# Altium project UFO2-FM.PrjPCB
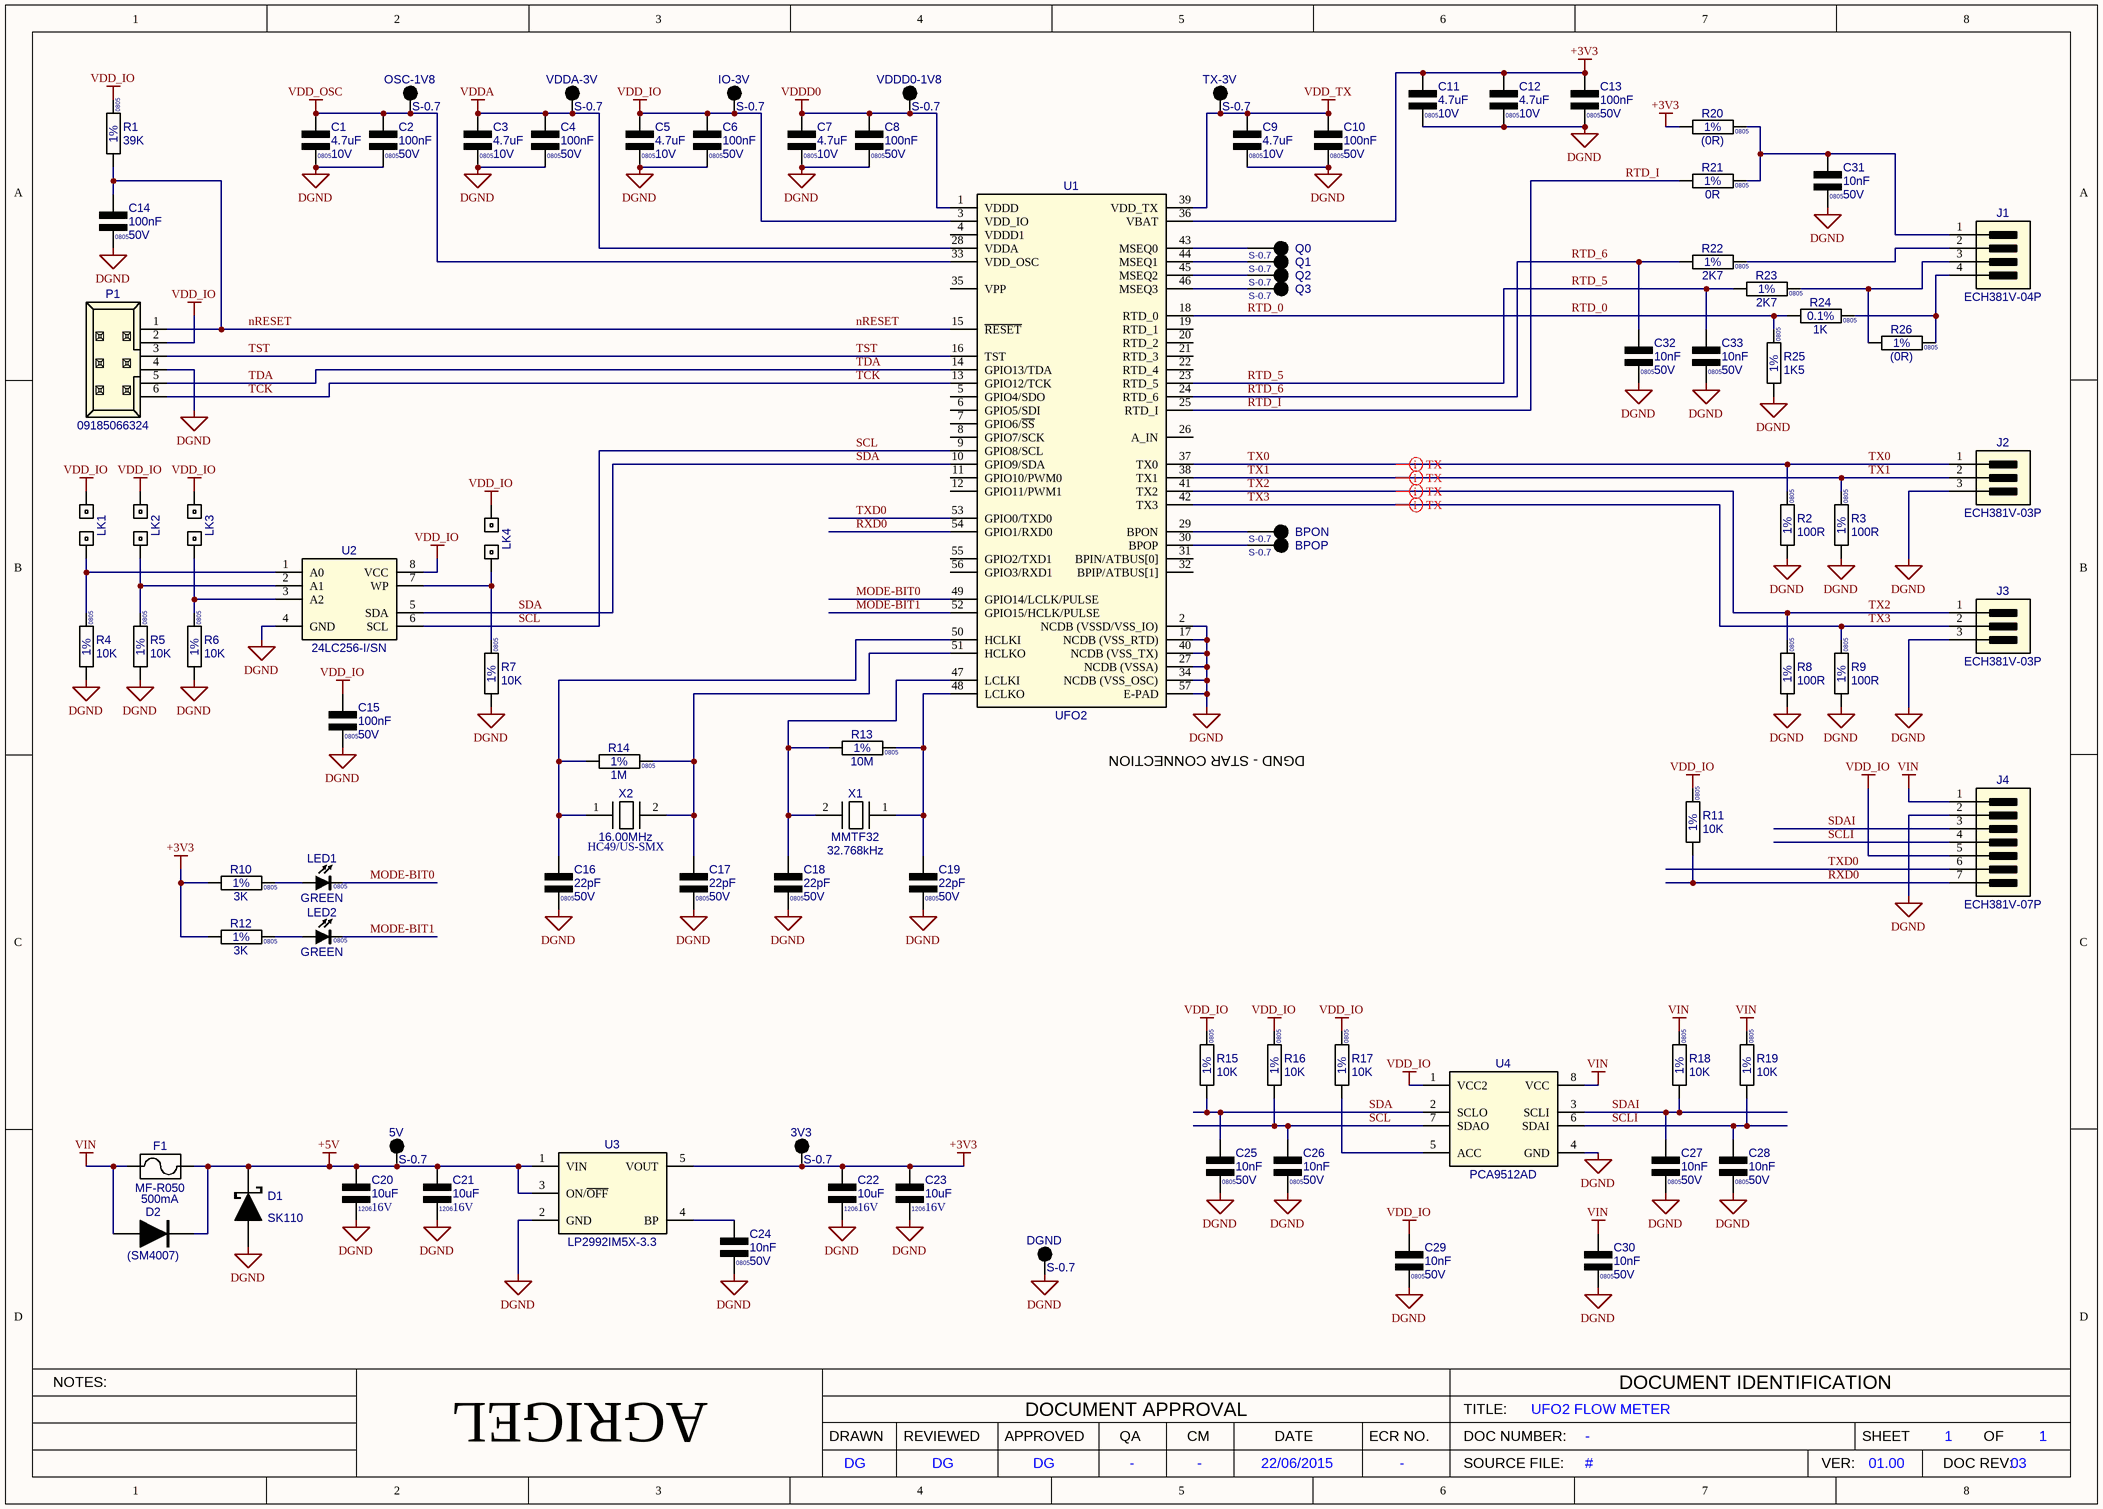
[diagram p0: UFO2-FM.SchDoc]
Version_PCB Assy Instruction: 3; Version: 01.00; Spec_Solder Mask: GREEN; Spec_Silkscreen: WHITE EPOXY; Spec_PCB Thickness: 1.60mm; Spec_Cu Thickness: 35um; SCH_Title: UFO2 FLOW METER; SCH_SheetTotal: 1; SCH_Reviewed: DG; SCH_QA: -; SCH_Number: -; SCH_FILENAME: UFO2-FM.SCH; SCH_ECR: -; SCH_DRAWN: DG; SCH_DocRev: 03; SCH_Date: 22/06/2015; SCH_CM: -; SCH_Approved: DG; PCB_TITLE: UFO2 FLOW METER PCB; PCB_Plot File [Assy]: UFO2-FM [Assy]; PCB_Plot File: UFO2-FM [Panel]; PCB_ECRNo: -; PCB_Drawn: EDM; PCB_Drawing Number: -; PCB_DocRevision: 03; PCB_Company Name: AGRIGEL
1 sheet, 93 parts. Net scope: global (net labels, ports and power ports of the same name join across sheets).
Board files: UFO2-FM.PcbDoc, UFO2-FM [Assy].PcbDoc, UFO2-FM [Panel].PcbDoc

## Sheet UFO2-FM.SchDoc: #
size A3; ApprovedBy: #; DrawnBy: #; DocumentNumber: 1; Revision: #; SheetNumber: 1; SheetTotal: 1; DocumentRevision: #; Reviewed: #; QA: #; CM: #; ECR: #; PageSetup: Record=PageOptions¦CenterHorizontal=True¦CenterVertical=True¦PrintScale=0.97¦XCorrection=1.00¦YCorrection=1.00¦PrintKind=1¦BorderSize=5000000¦LeftOffset=0¦BottomOffset=0¦Orientation=2¦PaperLength=1000¦PaperWidth=1000¦Scale=100¦PaperSource=7¦PrintQuality=-4¦MediaType=1¦DitherType=10¦PaperKind=A3¦PrintScaleMode=1

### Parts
3V3  Part Number: S-0.7  [TP-SMD-0.7MM]  (hidden comment: TP-SMD-0.7MM_V)
5V  Part Number: S-0.7  [TP-SMD-0.7MM]  (hidden comment: TP-SMD-0.7MM_V)
BPON  Part Number: S-0.7  [TP-SMD-0.7MM]  (hidden comment: TP-SMD-0.7MM)
BPOP  Part Number: S-0.7  [TP-SMD-0.7MM]  (hidden comment: TP-SMD-0.7MM)
C1  value 4.7uF  Voltage: 10V  Text1: 0805  [CAPC0805X110N]  (hidden comment: 4.7uF_C0805_10V_10%_X5R)
C2  value 100nF  Voltage: 50V  Text1: 0805  [CAPC0805X110N]  (hidden comment: 100nF_C0805_50V_10%_X7R)
C3  value 4.7uF  Voltage: 10V  Text1: 0805  [CAPC0805X110N]  (hidden comment: 4.7uF_C0805_10V_10%_X5R)
C4  value 100nF  Voltage: 50V  Text1: 0805  [CAPC0805X110N]  (hidden comment: 100nF_C0805_50V_10%_X7R)
C5  value 4.7uF  Voltage: 10V  Text1: 0805  [CAPC0805X110N]  (hidden comment: 4.7uF_C0805_10V_10%_X5R)
C6  value 100nF  Voltage: 50V  Text1: 0805  [CAPC0805X110N]  (hidden comment: 100nF_C0805_50V_10%_X7R)
C7  value 4.7uF  Voltage: 10V  Text1: 0805  [CAPC0805X110N]  (hidden comment: 4.7uF_C0805_10V_10%_X5R)
C8  value 100nF  Voltage: 50V  Text1: 0805  [CAPC0805X110N]  (hidden comment: 100nF_C0805_50V_10%_X7R)
C9  value 4.7uF  Voltage: 10V  Text1: 0805  [CAPC0805X110N]  (hidden comment: 4.7uF_C0805_10V_10%_X5R)
C10  value 100nF  Voltage: 50V  Text1: 0805  [CAPC0805X110N]  (hidden comment: 100nF_C0805_50V_10%_X7R)
C11  value 4.7uF  Voltage: 10V  Text1: 0805  [CAPC0805X110N]  (hidden comment: 4.7uF_C0805_10V_10%_X5R)
C12  value 4.7uF  Voltage: 10V  Text1: 0805  [CAPC0805X110N]  (hidden comment: 4.7uF_C0805_10V_10%_X5R)
C13  value 100nF  Voltage: 50V  Text1: 0805  [CAPC0805X110N]  (hidden comment: 100nF_C0805_50V_10%_X7R)
C14  value 100nF  Voltage: 50V  Text1: 0805  [CAPC0805X110N]  (hidden comment: 100nF_C0805_50V_10%_X7R)
C15  value 100nF  Voltage: 50V  Text1: 0805  [CAPC0805X110N]  (hidden comment: 100nF_C0805_50V_10%_X7R)
C16  value 22pF  Voltage: 50V  Text1: 0805  [CAPC0805X110N]  (hidden comment: 22pF_C0805_50V_10%_X7R)
C17  value 22pF  Voltage: 50V  Text1: 0805  [CAPC0805X110N]  (hidden comment: 22pF_C0805_50V_10%_X7R)
C18  value 22pF  Voltage: 50V  Text1: 0805  [CAPC0805X110N]  (hidden comment: 22pF_C0805_50V_10%_X7R)
C19  value 22pF  Voltage: 50V  Text1: 0805  [CAPC0805X110N]  (hidden comment: 22pF_C0805_50V_10%_X7R)
C20  value 10uF  Voltage: 16V  Text1: 1206  [CAPC1206X178N]  (hidden comment: 10uF_C1206_16V_5%_X7R)
C21  value 10uF  Voltage: 16V  Text1: 1206  [CAPC1206X178N]  (hidden comment: 10uF_C1206_16V_5%_X7R)
C22  value 10uF  Voltage: 16V  Text1: 1206  [CAPC1206X178N]  (hidden comment: 10uF_C1206_16V_5%_X7R)
C23  value 10uF  Voltage: 16V  Text1: 1206  [CAPC1206X178N]  (hidden comment: 10uF_C1206_16V_5%_X7R)
C24  value 10nF  Voltage: 50V  Text1: 0805  [CAPC0805X110N]  (hidden comment: 10nF_C0805_50V_10%_X7R)
C25  value 10nF  Voltage: 50V  Text1: 0805  [CAPC0805X110N]  (hidden comment: 10nF_C0805_50V_10%_X7R)
C26  value 10nF  Voltage: 50V  Text1: 0805  [CAPC0805X110N]  (hidden comment: 10nF_C0805_50V_10%_X7R)
C27  value 10nF  Voltage: 50V  Text1: 0805  [CAPC0805X110N]  (hidden comment: 10nF_C0805_50V_10%_X7R)
C28  value 10nF  Voltage: 50V  Text1: 0805  [CAPC0805X110N]  (hidden comment: 10nF_C0805_50V_10%_X7R)
C29  value 10nF  Voltage: 50V  Text1: 0805  [CAPC0805X110N]  (hidden comment: 10nF_C0805_50V_10%_X7R)
C30  value 10nF  Voltage: 50V  Text1: 0805  [CAPC0805X110N]  (hidden comment: 10nF_C0805_50V_10%_X7R)
C31  value 10nF  Voltage: 50V  Text1: 0805  [CAPC0805X110N]  (hidden comment: 10nF_C0805_50V_10%_X7R)
C32  value 10nF  Voltage: 50V  Text1: 0805  [CAPC0805X110N]  (hidden comment: 10nF_C0805_50V_10%_X7R)
C33  value 10nF  Voltage: 50V  Text1: 0805  [CAPC0805X110N]  (hidden comment: 10nF_C0805_50V_10%_X7R)
D1  Part Number: SK110  [SMA]  (hidden comment: SK110_SMA)
D2  value (SM4007)  [DO-213AB]  (hidden comment: SM4007-DNF)
DGND  Part Number: S-0.7  [TP-SMD-0.7MM]  (hidden comment: TP-SMD-0.7MM_V)
F1  value 500mA  [MF-R110]  (hidden comment: MF-R050)
IO-3V  Part Number: S-0.7  [TP-SMD-0.7MM]  (hidden comment: TP-SMD-0.7MM_V)
J1  ECH381V-04P  [ECH381V-04P]
J2  ECH381V-03P  [ECH381V-03P]
J3  ECH381V-03P  [ECH381V-03P]
J4  ECH381V-07P  [ECH381V-07P]
LED1  value GREEN  Text2: 0805  [LED0805-Green]  (hidden comment: GREEN_0805_SMD)
LED2  value GREEN  Text2: 0805  [LED0805-Green]  (hidden comment: GREEN_0805_SMD)
LK1  Link-THP-2.54-2PIN  [Link-THP-2.54-2PIN]  (value not drawn)
LK2  Link-THP-2.54-2PIN  [Link-THP-2.54-2PIN]  (value not drawn)
LK3  Link-THP-2.54-2PIN  [Link-THP-2.54-2PIN]  (value not drawn)
LK4  Link-THP-2.54-2PIN  [Link-THP-2.54-2PIN]  (value not drawn)
OSC-1V8  Part Number: S-0.7  [TP-SMD-0.7MM]  (hidden comment: TP-SMD-0.7MM_V)
P1  09185066324  [09185066324]
Q0  Part Number: S-0.7  [TP-SMD-0.7MM]  (hidden comment: TP-SMD-0.7MM)
Q1  Part Number: S-0.7  [TP-SMD-0.7MM]  (hidden comment: TP-SMD-0.7MM)
Q2  Part Number: S-0.7  [TP-SMD-0.7MM]  (hidden comment: TP-SMD-0.7MM)
Q3  Part Number: S-0.7  [TP-SMD-0.7MM]  (hidden comment: TP-SMD-0.7MM)
R1  value 39K  Tol: 1%  Text1: 0805  [RESC0805X65N]  (hidden comment: 39K_R0805_1%)
R2  value 100R  Tol: 1%  Text1: 0805  [RESC0805X65N]  (hidden comment: 100R_R0805_1%)
R3  value 100R  Tol: 1%  Text1: 0805  [RESC0805X65N]  (hidden comment: 100R_R0805_1%)
R4  value 10K  Tol: 1%  Text1: 0805  [RESC0805X65N]  (hidden comment: 10K_R0805_1%)
R5  value 10K  Tol: 1%  Text1: 0805  [RESC0805X65N]  (hidden comment: 10K_R0805_1%)
R6  value 10K  Tol: 1%  Text1: 0805  [RESC0805X65N]  (hidden comment: 10K_R0805_1%)
R7  value 10K  Tol: 1%  Text1: 0805  [RESC0805X65N]  (hidden comment: 10K_R0805_1%)
R8  value 100R  Tol: 1%  Text1: 0805  [RESC0805X65N]  (hidden comment: 100R_R0805_1%)
R9  value 100R  Tol: 1%  Text1: 0805  [RESC0805X65N]  (hidden comment: 100R_R0805_1%)
R10  value 3K  Tol: 1%  Text1: 0805  [RESC0805X65N]  (hidden comment: 3K_R0805_1%)
R11  value 10K  Tol: 1%  Text1: 0805  [RESC0805X65N]  (hidden comment: 10K_R0805_1%)
R12  value 3K  Tol: 1%  Text1: 0805  [RESC0805X65N]  (hidden comment: 3K_R0805_1%)
R13  value 10M  Tol: 1%  Text1: 0805  [RESC0805X65N]  (hidden comment: 10M_R0805_1%)
R14  value 1M  Tol: 1%  Text1: 0805  [RESC0805X65N]  (hidden comment: 1M_R0805_1%)
R15  value 10K  Tol: 1%  Text1: 0805  [RESC0805X65N]  (hidden comment: 10K_R0805_1%)
R16  value 10K  Tol: 1%  Text1: 0805  [RESC0805X65N]  (hidden comment: 10K_R0805_1%)
R17  value 10K  Tol: 1%  Text1: 0805  [RESC0805X65N]  (hidden comment: 10K_R0805_1%)
R18  value 10K  Tol: 1%  Text1: 0805  [RESC0805X65N]  (hidden comment: 10K_R0805_1%)
R19  value 10K  Tol: 1%  Text1: 0805  [RESC0805X65N]  (hidden comment: 10K_R0805_1%)
R20  value (0R)  Tol: 1%  Text1: 0805  [RESC0805X65N]  (hidden comment: 0R[NEQ]_R0805_1%)
R21  value 0R  Tol: 1%  Text1: 0805  [RESC0805X65N]  (hidden comment: 0R_R0805_1%)
R22  value 2K7  Tol: 1%  Text1: 0805  [RESC0805X65N]  (hidden comment: 2K7_R0805_1%)
R23  value 2K7  Tol: 1%  Text1: 0805  [RESC0805X65N]  (hidden comment: 2K7_R0805_1%)
R24  value 1K  Tol: 0.1%  Text1: 0805  [RESC0805X65N]  (hidden comment: 1K_R0805_0.1%)
R25  value 1K5  Tol: 1%  Text1: 0805  [RESC0805X65N]  (hidden comment: 1K5_R0805_1%)
R26  value (0R)  Tol: 1%  Text1: 0805  [RESC0805X65N]  (hidden comment: 0R[NEQ]_R0805_1%)
TX-3V  Part Number: S-0.7  [TP-SMD-0.7MM]  (hidden comment: TP-SMD-0.7MM_V)
U1  UFO2  [QFN56-8x8-EP]
U2  24LC256-I/SN  [SO8]
U3  LP2992IM5X-3.3  [SOT23-5]
U4  PCA9512AD  [SO8]
VDDA-3V  Part Number: S-0.7  [TP-SMD-0.7MM]  (hidden comment: TP-SMD-0.7MM_V)
VDDD0-1V8  Part Number: S-0.7  [TP-SMD-0.7MM]  (hidden comment: TP-SMD-0.7MM_V)
X1  32.768kHz  [MMTF32]
X2  Text2: HC49/US-SMX  Text1: 16.00MHz  [HC49/US-SMX-4.2]  (hidden comment: XTAL_16.00MHz-ACT-HC49/US-SMX)

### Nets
+3V3: 3V3.1 C11.1 C12.1 C13.1 C22.1 C23.1 R10.1 R12.1 R20.1 U1.36(VBAT) U3.5(VOUT)
+5V: 5V.1 C20.1 C21.1 D1.1(C) D2.1(C) F1.2 U3.1(VIN) U3.3(ON/~{OFF})
DGND: C1.2 C2.2 C3.2 C4.2 C5.2 C6.2 C7.2 C8.2 C9.2 C10.2 C11.2 C12.2 C13.2 C14.2 C15.2 C16.2 C17.2 C18.2 C19.2 C20.2 C21.2 C22.2 C23.2 C24.2 C25.2 C26.2 C27.2 C28.2 C29.2 C30.2 C31.2 C32.2 C33.2 D1.2(A) DGND.1 J2.3 J3.3 J4.2 P1.4 R2.2 R3.2 R4.2 R5.2 R6.2 R7.2 R8.2 R9.2 R25.2 U1.2(NCDB_(VSSD/VSS_IO)) U1.17(NCDB_(VSS_RTD)) U1.27(NCDB_(VSSA)) U1.34(NCDB_(VSS_OSC)) U1.40(NCDB_(VSS_TX)) U1.57(E-PAD) U2.4(GND) U3.2(GND) U4.4(GND)
VDD_IO: C5.1 C6.1 C15.1 C29.1 IO-3V.1 J4.5 LK1.1 LK2.1 LK3.1 LK4.1 P1.2 R1.1 R11.1 R15.1 R16.1 R17.1 U1.3(VDD_IO) U2.8(VCC) U4.1(VCC2)
VDD_OSC: C1.1 C2.1 OSC-1V8.1 U1.33(VDD_OSC)
VDD_TX: C9.1 C10.1 TX-3V.1 U1.39(VDD_TX)
VDDA: C3.1 C4.1 U1.28(VDDA) VDDA-3V.1
VDDD0: C7.1 C8.1 U1.1(VDDD) VDDD0-1V8.1
VIN: C30.1 D2.2(A) F1.1 J4.1 R18.1 R19.1 U4.8(VCC)
MODE-BIT0: LED1.1(K) U1.49(GPIO14/LCLK/PULSE)
MODE-BIT1: LED2.1(K) U1.52(GPIO15/HCLK/PULSE)
nRESET: C14.1 P1.1 R1.2 U1.15(~{RESET})
RTD_0: R24.1 R25.1 U1.18(RTD_0)
RTD_5: C33.1 R23.1 U1.23(RTD_5)
RTD_6: C32.1 R22.1 U1.24(RTD_6)
RTD_I: R21.1 U1.25(RTD_I)
RXD0: J4.7 R11.2 U1.54(GPIO1/RXD0)
SCL: C26.1 R16.2 U1.9(GPIO8/SCL) U2.6(SCL) U4.7(SDAO)
SCLI: C28.1 J4.4 R19.2 U4.6(SDAI)
SDA: C25.1 R15.2 U1.10(GPIO9/SDA) U2.5(SDA) U4.2(SCLO)
SDAI: C27.1 J4.3 R18.2 U4.3(SCLI)
TCK: P1.6 U1.13(GPIO12/TCK)
TDA: P1.5 U1.14(GPIO13/TDA)
TST: P1.3 U1.16(TST)
TX0: J2.1 R2.1 U1.37(TX0)
TX1: J2.2 R3.1 U1.38(TX1)
TX2: J3.1 R8.1 U1.41(TX2)
TX3: J3.2 R9.1 U1.42(TX3)
TXD0: J4.6 U1.53(GPIO0/TXD0)
NetBPON_1: BPON.1 U1.29(BPON)
NetBPOP_1: BPOP.1 U1.30(BPOP)
NetC16_1: C16.1 R14.1 U1.50(HCLKI) X2.1
NetC17_1: C17.1 R14.2 U1.51(HCLKO) X2.2
NetC18_1: C18.1 R13.1 U1.47(LCLKI) X1.2
NetC19_1: C19.1 R13.2 U1.48(LCLKO) X1.1
NetC24_1: C24.1 U3.4(BP)
NetC31_1: C31.1 J1.1 R20.2 R21.2
NetJ1_2: J1.2 R22.2
NetJ1_3: J1.3 R23.2 R26.1
NetJ1_4: J1.4 R24.2 R26.2
NetLED1_2: LED1.2(A) R10.2
NetLED2_2: LED2.2(A) R12.2
NetLK1_2: LK1.2 R4.1 U2.1(A0)
NetLK2_2: LK2.2 R5.1 U2.2(A1)
NetLK3_2: LK3.2 R6.1 U2.3(A2)
NetLK4_2: LK4.2 R7.1 U2.7(WP)
NetQ0_1: Q0.1 U1.43(MSEQ0)
NetQ1_1: Q1.1 U1.44(MSEQ1)
NetQ2_1: Q2.1 U1.45(MSEQ2)
NetQ3_1: Q3.1 U1.46(MSEQ3)
NetR17_2: R17.2 U4.5(ACC)

Not connected (* = marked no-connect by the designer): U1 4(VDDD1) 5(GPIO4/SDO) 6(GPIO5/SDI) 7(GPIO6/~{SS}) 8(GPIO7/SCK) 11(GPIO10/PWM0) 12(GPIO11/PWM1) 19(RTD_1) 20(RTD_2) 21(RTD_3) 22(RTD_4) 26(A_IN) 31(BPIN/ATBUS[0]) 32(BPIP/ATBUS[1]) 35(VPP) 55(GPIO2/TXD1) 56(GPIO3/RXD1)

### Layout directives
rule Length Constraint [Min Length = 2030mil    Max Length = 2050mil]: TX0, TX1, TX2, TX3

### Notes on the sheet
- DGND - STAR CONNECTION

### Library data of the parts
3V3 5V DGND IO-3V OSC-1V8 TX-3V VDDA-3V VDDD0-1V8 = TP-SMD-0.7MM_V: Test Point Surface Mount 0.7mm Pad; Manufacturer: Generic; Board Tech: SMD
BPON BPOP Q0-Q3 = TP-SMD-0.7MM: Test Point Surface Mount 0.7mm Pad; Manufacturer: Generic; Board Tech: SMD
C1 C3 C5 C7 C9 C11 C12 = 4.7uF_0805N_10V_10%_X5R_V: Cap Ceramic X5R; Manufacturer: Various; Part Number: 4.7uF 0805 10V 10% X5R; Board Tech: SMD; Tol: 10%; Reutech PN: 5910-CA-0468
C2 C4 C6 C8 C10 C13-C15 = 100nF_0805N_50V_10%_X7R_V: Cap Ceramic X7R; Manufacturer: Various; Part Number: 100nF 0805 50V 10% X7R; Board Tech: SMD; EDM-PN: CAP42; Tol: 10%; Reutech PN: 5910-CA-0122
C16-C19 = 22pF_0805N_50V_10%_X7R_V: Cap Ceramic X7R; Manufacturer: Various; Part Number: 22pF 0805 50V 10% X7R; Board Tech: SMD; EDM-PN: CAP406; Tol: 10%
C20-C23 = 10uF_1206N_16V_5%_X7R_V: Cap Ceramic X7R; Manufacturer: Various; Part Number: 10uF 1206 16V 5% X7R; Board Tech: SMD; Tol: 5%; Reutech PN: 5910-CA-0434
C24-C33 = 10nF_0805N_50V_10%_X7R_V: Cap Ceramic X7R; Manufacturer: Various; Part Number: 10nF 0805 50V 10% X7R; Board Tech: SMD; EDM-PN: CAP5; Tol: 10%
D1 = SK110_SMA_V: Diode Schottky Rectifier 1Amp 100V; Manufacturer: Diotec; Board Tech: SMD; Value: SK110
D2 = SM4007_H-DNF: Diode Rectifier 1Amp 1000V - Do no Fit; Manufacturer: Diotec; Part Number: DNF - SM4007; Board Tech: SMD; EDM-PN: DIO19
F1 = PolyFuse-MF-R050: PTC Resettable Fuse 500mA 60V; Manufacturer: Bourns; Board Tech: THP
J1 = ECH381V-04P: Header Pluggable 3.81mm Vertical; Manufacturer: Dinkle; Board Tech: THP
J2 J3 = ECH381V-03P: Header Pluggable 3.81mm Vertical; Manufacturer: Dinkle; Board Tech: THP
J4 = ECH381V-07P: Header Pluggable 3.81mm Vertical; Manufacturer: Dinkle; Board Tech: THP
LED1 LED2 = GREEN_0805_SMD_H: LED SMD 0805 Green; Manufacturer: Various; EDM-PN: LED17
LK1-LK4 = Link-THP-2.54-2PIN: Link THP Open 2.54mm; Manufacturer: Generic; Part Number: LINK-THP-2P
P1 = 09185066324: Header Box Male Straight 2.54mm Pitch; Manufacturer: Harting; Board Tech: THP
R1 = 39K_0805_V: Resistor Chip SMD; Manufacturer: Various; Part Number: 39K 0805 1%; Watt: 125mW; EDM-PN: RES188
R2 R3 R8 R9 = 100R_0805_V: Resistor Chip SMD; Manufacturer: Various; Part Number: 100R 0805 1%; Watt: 125mW
R4-R7 R11 R15-R19 = 10K_0805_V: Resistor Chip SMD; Manufacturer: Various; Part Number: 10K 0805 1%; Watt: 125mW; EDM-PN: RES8
R10 R12 = 3K_0805_H: Resistor Chip SMD; Manufacturer: Various; Part Number: 3K 0805 1%; Watt: 125mW
R13 = 10M_0805_H: Resistor Chip SMD; Manufacturer: Various; Part Number: 10M 0805 1%; Watt: 125mW
R14 = 1M_0805_H: Resistor Chip SMD; Manufacturer: Various; Part Number: 1M 0805 1%; Watt: 125mW; EDM-PN: RES421
R20 R26 = 0R_0805_H-DNF: Resistor Chip SMD - Do not Fit; Manufacturer: Various; Part Number: DNF - 0R 0805 1%; Watt: 125mW
R21 = 0R_0805_H: Resistor Chip SMD; Manufacturer: Various; Part Number: 0R 0805 1%; Watt: 125mW; EDM-PN: RES58
R22 R23 = 2K7_0805_H: Resistor Chip SMD; Manufacturer: Various; Part Number: 2K7 0805 1%; Watt: 125mW
R24 = 1K_0805_H-0.1%: Resistor Chip SMD; Manufacturer: Various; Part Number: 1K 0805 0.1%; Watt: 125mW
R25 = 1K5_0805_V: Resistor Chip SMD; Manufacturer: Various; Part Number: 1K5 0805 1%; Watt: 125mW
U1 = UFO2_QFN56: IC D-Flow ASIC; Manufacturer: D-Flow Technology; Board Tech: SMD
U2 = 24LC256-I/SN-SO8: IC 256K I2C Serial EEPROM; Manufacturer: Microchip; Board Tech: SMD
U3 = LP2992IM5X-3.3_SOT23-5N: Voltage Regulator Ultra LDO 250mA; Manufacturer: National; Board Tech: SMD
U4 = PCA9512AD_SO8: IC Level-Shifting I2C Bus and SMBus Buffer; Manufacturer: NXP; Board Tech: SMD
X1 = XTAL_32.768kHz_MMTF32: Crystal - MMTF32; Manufacturer: Jaugh; Board Tech: THP; Value: Q 0.032768 MMTF32 12.5 20
X2 = XTAL_16.00MHz-ACT-HC49/US-SMX: Crystal - ACT HC49/US-SMX; Manufacturer: Abracon; Part Number: HC49US-18M4320-B4H-T; Board Tech: SMD; Value: 16.00MHZ-HC49/US-SMX

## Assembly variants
Variant of UFO2-FM: not fitted C25 C26 C27 C28 R20 R26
